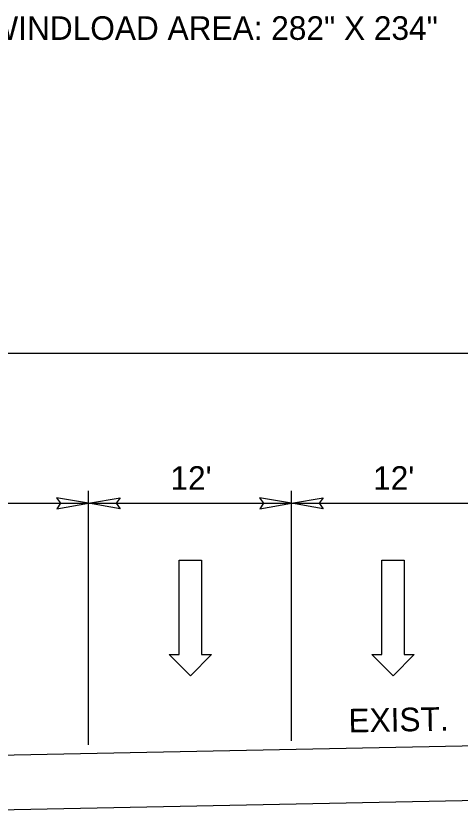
# Model space of a CAD drawing. Extents: x 1726582 to 1728895, y 538986 to 541550.
# Drawn here: x 1727265.4 to 1727397, y 541308.8 to 541545.1 of the extents above; entities that cross this region are included whole.
import ezdxf

# ---------------------------------------------------------------- set-up
doc = ezdxf.new("R2010")
doc.units = 0
for name, color, linetype in [('Default', 7, 'Continuous'), ('GSProposed', 7, 'Continuous'), ('GSReplace', 7, 'Continuous')]:
    doc.layers.add(name, color=color, linetype=linetype)

msp = doc.modelspace()

# ---------------------------------------------------------------- linework, layer by layer
at = {"layer": 'Default'}
for p, q in [((1727250.93, 541445), (1727880.5, 541445)), ((1727286.83, 541328.77), (1727286.83, 541404.16)), ((1727346.99, 541329.98), (1727346.99, 541404.16)), ((1727226.89, 541400.46), (1727286.94, 541400.46)), ((1727286.94, 541400.46), (1727346.99, 541400.46)), ((1727346.99, 541400.46), (1727407.04, 541400.46)), ((1727313.73, 541355.56), (1727313.73, 541383.56)), ((1727313.73, 541383.56), (1727320.33, 541383.56)), ((1727320.33, 541383.56), (1727320.33, 541355.56)), ((1727373.78, 541355.56), (1727373.78, 541383.56)), ((1727373.78, 541383.56), (1727380.38, 541383.56)), ((1727380.38, 541383.56), (1727380.38, 541355.56)), ((1727317.13, 541349.26), (1727310.73, 541355.56)), ((1727310.73, 541355.56), (1727313.73, 541355.56)), ((1727323.33, 541355.56), (1727317.13, 541349.26)), ((1727320.33, 541355.56), (1727323.33, 541355.56)), ((1727377.18, 541349.26), (1727370.78, 541355.56)), ((1727370.78, 541355.56), (1727373.78, 541355.56)), ((1727383.38, 541355.56), (1727377.18, 541349.26)), ((1727380.38, 541355.56), (1727383.38, 541355.56))]:
    msp.add_line(p, q, dxfattribs=at)
for points in [[(1727277.46, 541398.85), (1727286.83, 541400.46), (1727277.4, 541402.13), (1727278.6, 541400.46)], [(1727296.21, 541398.85), (1727286.83, 541400.46), (1727296.26, 541402.13), (1727295.07, 541400.46)], [(1727337.61, 541398.85), (1727346.99, 541400.46), (1727337.56, 541402.13), (1727338.76, 541400.46)], [(1727356.37, 541398.85), (1727346.99, 541400.46), (1727356.42, 541402.13), (1727355.22, 541400.46)]]:
    msp.add_lwpolyline(points, close=True, dxfattribs=at)
at = {"layer": 'GSReplace'}
for p, q in [((1727226.79, 541325.1), (1727461.04, 541329.79)), ((1727226.79, 541308.85), (1727461.04, 541313.53))]:
    msp.add_line(p, q, dxfattribs=at)

# ---------------------------------------------------------------- texts
at = {"layer": 'GSProposed'}
for s, height, p in [('WINDLOAD AREA: 282" X 234"', 7.0055, (1727257.21, 541537.98)), ("12'", 7.005, (1727311.15, 541404.47)), ("12'", 7.005, (1727371.2, 541404.47))]:
    msp.add_text(s, height=height, dxfattribs=at).set_placement(p)
msp.add_text('EXIST.', height=7.005, rotation=1.1457, dxfattribs=at).set_placement((1727363.97, 541332.45))

doc.saveas('drawing.dxf')
